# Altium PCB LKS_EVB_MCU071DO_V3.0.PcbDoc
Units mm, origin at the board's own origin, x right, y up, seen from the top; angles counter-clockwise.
Board outline 66.67 x 39.62 mm, 2 copper layers (Top Layer, Bottom Layer); 43 components, 55 nets, 188 pads, 243 vias.
Unrouted connection lines stored in the file: 4.
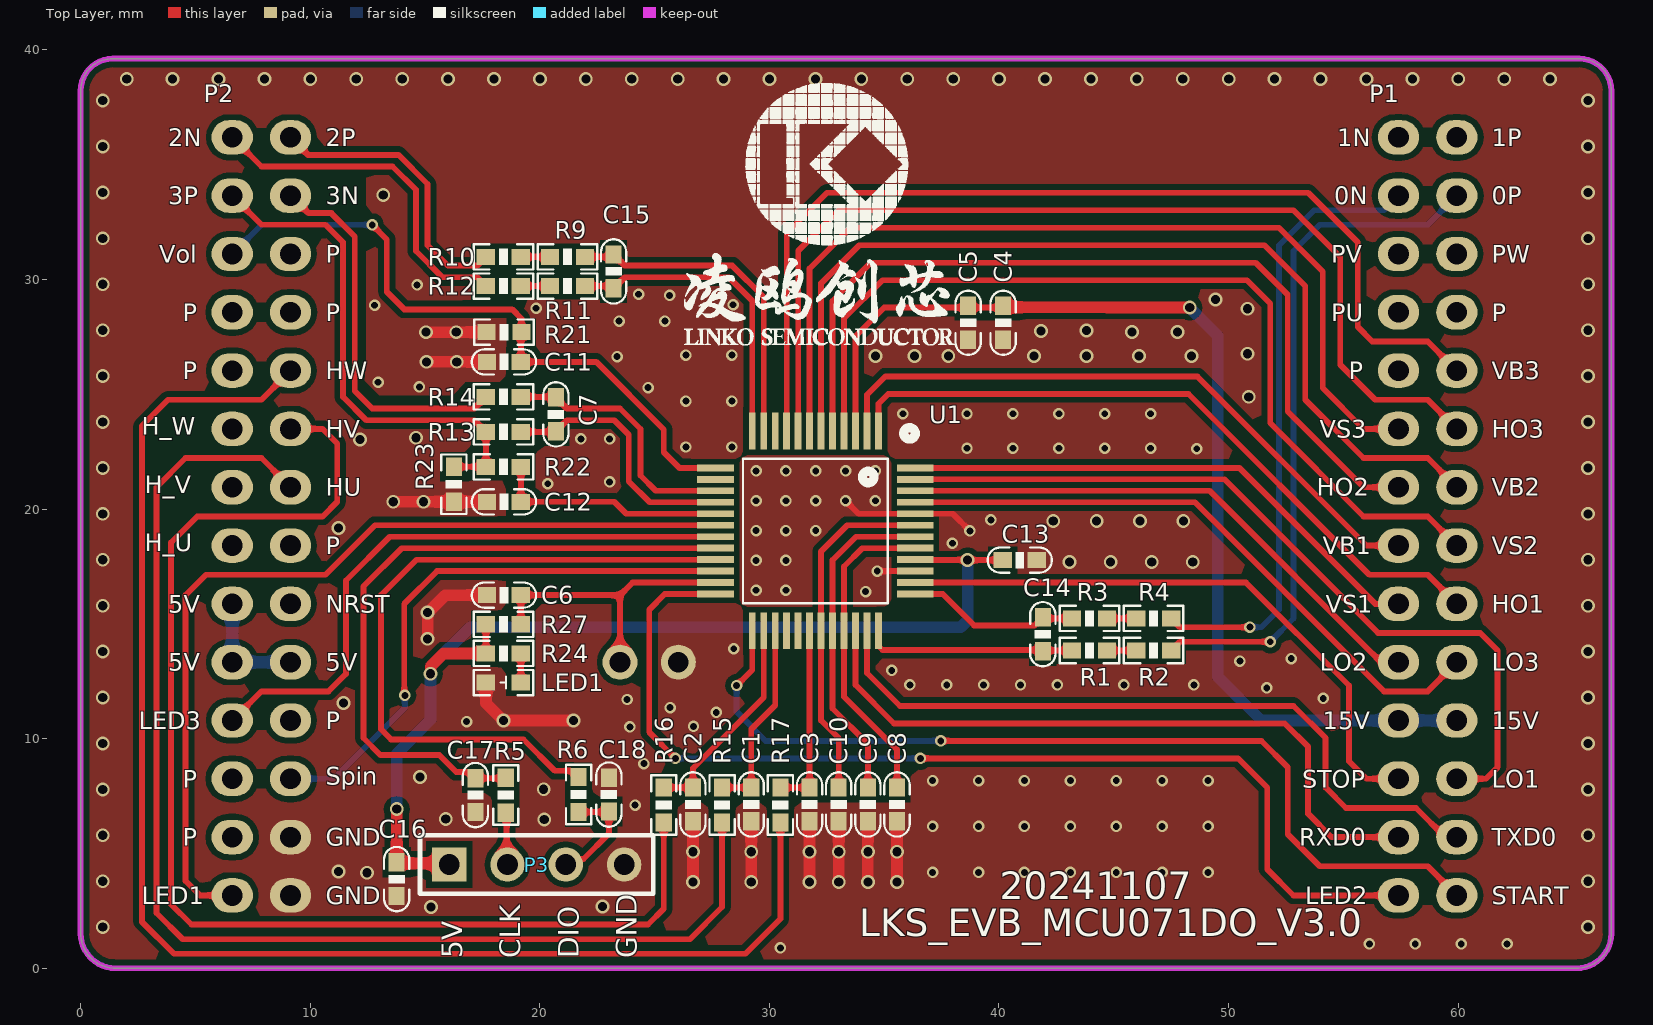
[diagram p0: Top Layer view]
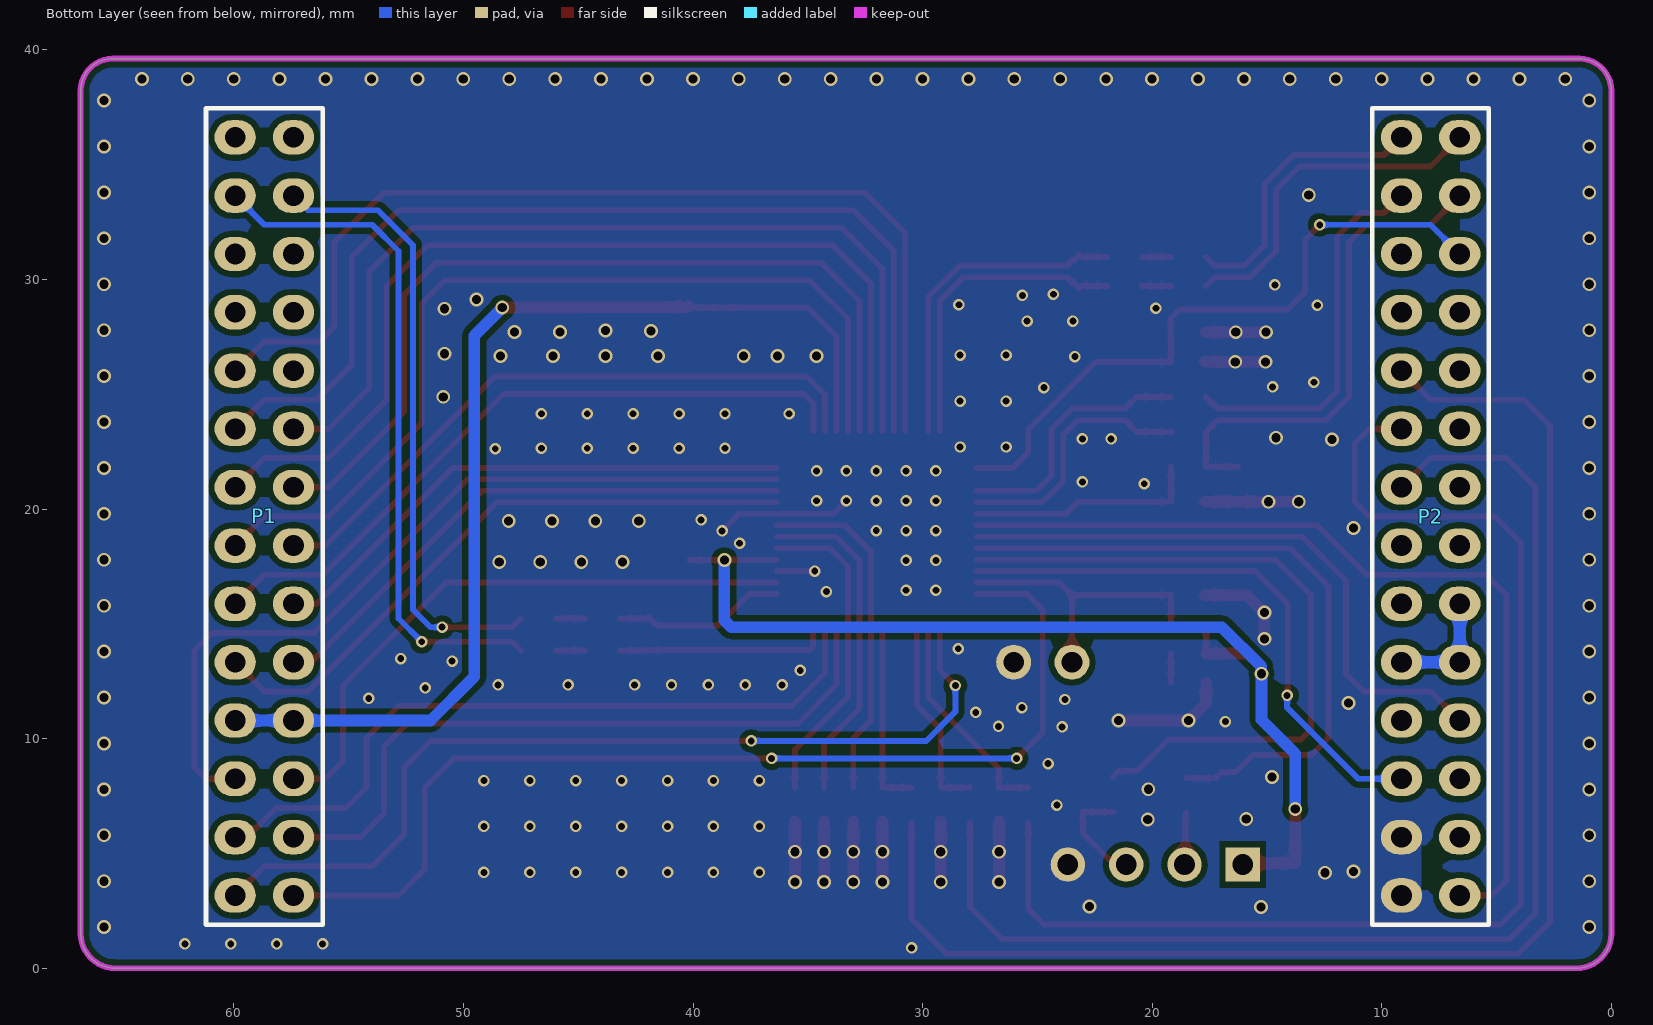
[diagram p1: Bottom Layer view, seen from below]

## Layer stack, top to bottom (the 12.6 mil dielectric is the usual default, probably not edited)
Top Solder: solder mask 0.0102, Solder Resist, Dk 3.5
Top Layer: signal copper 0.0356
Dielectric1: dielectric 0.32, FR-4, Dk 4.8
Bottom Layer: signal copper 0.0356
Bottom Solder: solder mask 0.0102, Solder Resist, Dk 3.5

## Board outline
0,1.524 0,38.227 cw(c1.397,38.227) 1.397,39.624 65.278,39.624 cw(c65.278,38.227) 66.675,38.227 66.675,1.524 cw(c65.151,1.524) 65.151,0 1.524,0 cw(c1.524,1.524)

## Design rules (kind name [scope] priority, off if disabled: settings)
Clearance Clearance_MCU [All] p1: gap=0.254 ignorepadtopadclearanceinfootprint=FALSE except(0.198: Arc-Arc Arc-Track Arc-SMDPad Track-Track Track-SMDPad SMDPad-SMDPad)
Clearance [All] p2: gap=0.254 ignorepadtopadclearanceinfootprint=FALSE
ComponentClearance [All] p1: gap=0 collisioncheckmode=3 verticalgap=0 showdistances=FALSE
FabricationTestpoint [(IsPad And (OnTopLayer Or OnBottomLayer))] p1: side=3 testpointundercomponent=TRUE minsize=1.016 maxsize=2.54 preferedsize=1.524 minholesize=0 maxholesize=1.016 preferedholesize=0.813 testpointgrid=0.025 allowsidetop=TRUE allowsidebottom=TRUE usegrid=TRUE gridtolerance=0
HoleSize [All] p1: absolutevalues=TRUE maxlimit=2.54 minlimit=0 maxpercent=80.000 minpercent=20.000
PolygonConnect PolygonConnect_1 [HasFootprint('HDR 2X14 顶层') vs InNet('GND')] p1: connectstyle=Direct reliefconductorwidth=0.508 reliefentries=4 polygonreliefangle="90 Angle" airgapwidth=0.254
PolygonConnect [All] p2: connectstyle=Direct reliefconductorwidth=0.254 reliefentries=4 polygonreliefangle="90 Angle" airgapwidth=0.254
RoomDefinition MCU [InComponentClass('Components Class1') vs False] p1: confinementstyle=ConfineIn formatcopy=TRUE lockcomponents=FALSE outline 25.857,28.296 27.381,29.82 27.381,32.893 30.432,32.893 32.003,34.464 35.995,34.464 35.995,29.664 41.427,24.232 49.479,24.232 51.841,21.869 49.378,19.406 42.977,19.406 34.315,10.744 26.34,10.744 26.34,12.065 22.885,15.519 23.266,15.9 23.266,28.169
RoutingVias [All] p1: holewidth=0.711 width=1.27 viastyle="Through Hole" minholewidth=0 minwidth=0.254 maxholewidth=0.711 maxwidth=1.27
SilkToSolderMaskClearance SilkscreenOverComponentPads [IsPad] p1: minsilkscreentomaskgap=0.254 clearancetoexposedcopper=TRUE
SolderMaskExpansion [All] p1: expansion=0.102 istentingtop=FALSE
Width [All] p1: maxlimit=2.54 minlimit=0.025 preferedwidth=0.254
26 further rules are at their usual default settings.

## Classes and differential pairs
component class "Components Class1": U1

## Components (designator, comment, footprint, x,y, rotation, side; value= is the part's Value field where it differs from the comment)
C1 "10nF/16V" 0603C 29.21,7.137 r270 top
C2 "10nF/16V" 0603C 26.67,7.137 r270 top
C3 "10nF/16V" 0603C 31.75,7.137 r270 top
C4 "10uF/25V" 0603C 40.183,28.118 r90 top
C5 "100nF/50V" 0603C 38.659,28.118 r90 top
C6 "100nF/50V" 0603C 18.44,16.256 r180 top
C7 "1uF/50V" 0603C 20.701,24.13 r90 top
C8 "1nF/50V" 0603C 35.56,7.137 r270 top
C9 "1nF/50V" 0603C 34.29,7.137 r270 top
C10 "1nF/50V" 0603C 33.02,7.137 r270 top
C11 "100nF/50V" 0603C 18.439,26.416 r0 top
C12 "1nF/50V" 0603C 18.439,20.32 r0 top
C13 "1uF/16V" 0603C 40.907,17.78 r180 top
C14 "100pF/50V" 0603C 41.91,14.554 r270 top
C15 "100pF/50V" 0603C 23.216,30.353 r90 top
C16 "100nF/50V" 0603C 13.767,3.886 r270 top
C17 "20pF/50V" 0603C 17.196,7.544 r90 top
C18 "20pF/50V" 0603C 23.009,7.569 r270 top
LED1 "LED" "LED 0603R" 18.415,12.446 r180 top
P1 "Header 14X2A" "HDR 2X14 顶层" 58.674,19.685 r180 bottom locked
P2 "Header 14X2A" "HDR 2X14 顶层" 7.874,19.685 r180 bottom locked
P3 "Header 4" "HDR 1X4" 16.053,4.521 r0 top
R1 "1K1%" 0603R 43.942,13.843 r180 top value=K
R2 "0R1%" 0603R 46.736,13.843 r180 top value=K
R3 "1K1%" 0603R 43.942,15.24 r180 top value=K
R4 "0R%" 0603R 46.736,15.24 r180 top value=K
R5 "120R1%" 0603R 18.517,7.544 r270 top value=K
R6 "120R1%" 0603R 21.688,7.569 r270 top value=K
R9 "1K1%" 0603R 21.209,30.988 r0 top value=K
R10 "0R1%" 0603R 18.415,30.988 r0 top value=K
R11 "1K1%" 0603R 21.209,29.718 r0 top value=K
R12 "0R1%" 0603R 18.415,29.718 r0 top value=K
R13 "1K1%" 0603R 18.415,23.368 r0 top value=K
R14 "1K1%" 0603R 18.415,24.892 r0 top value=K
R15 "2K" 0603R 27.94,7.112 r90 top value=K
R16 "2K" 0603R 25.4,7.112 r90 top value=K
R17 "2K" 0603R 30.48,7.112 r90 top value=K
R21 "1K1%" 0603R 18.439,27.71 r0 top value=K
R22 "1K1%" 0603R 18.415,21.844 r180 top value=K
R23 "10R" 0603R 16.256,21.082 r270 top value=K
R24 "330R" 0603R 18.415,13.716 r0 top value=K
R27 "10K1%" 0603R 18.415,14.986 r180 top value=K
U1 "LKS32MC071DOC8T8" TQFP48 32.004,19.05 r180 top locked

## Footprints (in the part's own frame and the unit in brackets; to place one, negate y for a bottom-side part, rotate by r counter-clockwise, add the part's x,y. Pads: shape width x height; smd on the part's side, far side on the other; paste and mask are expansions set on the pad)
0603C [mm] "电容"
  rect 0.8x0.7 smd: 1(-0.737,0) 2(0.738,0)
  silkscreen extent -1.4,-0.55 1.4,0.55, body extent -0.8,-0.41 0.8,0.41, height 0.81
0603R [mm] "电阻"
  rect 0.8x0.7 smd: 1(-0.762,0) 2(0.762,0)
  silkscreen extent -1.3,-0.55 1.3,0.55, body extent -0.8,-0.4 0.8,0.4, height 0.45
"HDR 1X4" [mm] "单排针 2.54mm"
  rect 1.5x1.5 hole 0.9: 1(0,0)
  round 1.5 hole 0.9: 2(2.54,0) 3(5.08,0) 4(7.62,0)
  silkscreen extent -1.27,-1.27 8.89,1.27, body extent -1.27,-1.27 8.89,1.27, height 8.5
"HDR 2X14 顶层" [mm] "双排针 2.54mm 顶层"
  oval 1.8x1.5 hole 0.9: 1(1.27,16.51) 2(1.27,13.97) 3(1.27,11.43) 4(1.27,8.89) 5(1.27,6.35) 6(1.27,3.81) 7(1.27,1.27) 8(1.27,-1.27) 9(1.27,-3.81) 10(1.27,-6.35) 11(1.27,-8.89) 12(1.27,-11.43) 13(1.27,-13.97) 14(1.27,-16.51) 15(-1.27,16.51) 16(-1.27,13.97) 17(-1.27,11.43) 18(-1.27,8.89) 19(-1.27,6.35) 20(-1.27,3.81) 21(-1.27,1.27) 22(-1.27,-1.27) 23(-1.27,-3.81) 24(-1.27,-6.35) 25(-1.27,-8.89) 26(-1.27,-11.43) 27(-1.27,-13.97) 28(-1.27,-16.51)
  silkscreen extent -2.54,-17.78 2.54,17.78, body extent -2.54,-17.78 2.54,17.78, height 8.5
"LED 0603R" [mm] "LED"
  rect 0.8x0.7 smd: 1(-0.762,0) 2(0.762,0)
  silkscreen extent -1.3,-0.55 1.3,0.55, body extent -0.8,-0.4 0.8,0.4, height 0.47
TQFP48 [mm] "MCU"
  rect 0.3x1.6 smd: 1(-2.75,-4.35) 2(-2.25,-4.35) 3(-1.75,-4.35) 4(-1.25,-4.35) 5(-0.75,-4.35) 6(-0.25,-4.35) 7(0.25,-4.35) 8(0.75,-4.35) 9(1.25,-4.35) 10(1.75,-4.35) 11(2.25,-4.35) 12(2.75,-4.35) 25(2.75,4.35) 26(2.25,4.35) 27(1.75,4.35) 28(1.25,4.35) 29(0.75,4.35) 30(0.25,4.35) 31(-0.25,4.35) 32(-0.75,4.35) 33(-1.25,4.35) 34(-1.75,4.35) 35(-2.25,4.35) 36(-2.75,4.35)
  rect 1.6x0.3 smd: 13(4.35,-2.75) 14(4.35,-2.25) 15(4.35,-1.75) 16(4.35,-1.25) 17(4.35,-0.75) 18(4.35,-0.25) 19(4.35,0.25) 20(4.35,0.75) 21(4.35,1.25) 22(4.35,1.75) 23(4.35,2.25) 24(4.35,2.75) 37(-4.35,2.75) 38(-4.35,2.25) 39(-4.35,1.75) 40(-4.35,1.25) 41(-4.35,0.75) 42(-4.35,0.25) 43(-4.35,-0.25) 44(-4.35,-0.75) 45(-4.35,-1.25) 46(-4.35,-1.75) 47(-4.35,-2.25) 48(-4.35,-2.75)
  silkscreen extent -4.35,-4.5 3.15,3.15, body extent -4.5,-4.5 4.5,4.5, height 1.05

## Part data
C1 C2 C3 C8 C9 C10: library part CAP, "Capacitor"
C4 C5 C6 C7 C11 C12 C13 C14 C15 C16 C17 C18: library part C, "Capacitor"
LED1: "LED_Light"
P1 P2: "Header, 14-Pin, Dual row"
P3: "Header, 4-Pin"
R1 R2 R3 R4 R5 R6 R9 R10 R11 R12 R13 R14 R15 R16 R17 R21 R22 R23 R24 R27: library part Res, "Resistor"
U1: "芯片"

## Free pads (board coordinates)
  round 1.524 hole 0.9: 0(26.035,13.335) 1(23.495,13.335)

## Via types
v1: diameter 0.6, hole 0.4, Top Layer to Bottom Layer, 132 vias
v2: diameter 0.5, hole 0.3, Top Layer to Bottom Layer, 111 vias

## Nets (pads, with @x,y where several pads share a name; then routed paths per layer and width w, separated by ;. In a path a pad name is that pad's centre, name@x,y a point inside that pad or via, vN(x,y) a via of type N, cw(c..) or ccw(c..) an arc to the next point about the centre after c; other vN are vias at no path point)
5V: C13.2 C16.1 P3.1 R24.1 R27.2 U1.40 | length 46.4
  Top Layer w0.254: R24.1 R27.2 ; U1.40 36.364,17.79 38.623,17.79 v1(38.633,17.78) C13.2
  Top Layer w0.508: C16.1@13.767,4.573 C16.1 ; v1(13.767,6.934) C16.1 ; v1(15.24,12.827) 15.258,12.845 15.258,13.149 15.824,13.716 R24.1 ; P3.1 16.002,4.572 13.818,4.572 13.792,4.598 C16.1
  Bottom Layer w0.508: v1(13.767,6.934) 13.767,9.347 15.24,10.82 v1(15.24,12.827) 15.258,12.845 15.258,13.149 16.967,14.859 38.336,14.859 38.633,15.157 v1(38.633,17.78)
+5V: P2.9 P2.10 P2.24 | length 5.1
  Bottom Layer w0.508: P2.9 P2.10 P2.24
+15V: C4.2 C5.2 P1.11 P1.25 U1.3 | length 53.6
  Top Layer w0.254: U1.3 33.754,27.531 35.003,28.78 43.18,28.78
  Top Layer w0.508: C4.2 40.241,28.797 48.292,28.797 v1(48.309,28.78) 44.704,28.78
  Bottom Layer w0.508: v1(48.309,28.78) 49.53,27.559 49.53,12.7 51.435,10.795 P1.11 P1.25
GND: C1.2 C2.2 C3.2 C4.1 C5.1 C6.2 C8.2 C9.2 C10.2 C11.1 C12.1 C13.1 C16.2 C17.1 C18.1 LED1.2 P2.16 P2.27 P2.28 P3.4 pad.0 R14.1 R21.1 R23.2 U1.39 U1.44 | length 58.4
  Top Layer w0.254: P2.16 9.159,33.655 9.921,32.893 10.922,32.893 11.938,31.877 11.938,25.146 12.7,24.384 17.145,24.384 R14.1 ; v2(33.32,20.366) 33.886,19.8 U1.44 37.985,19.8 v2(38.735,19.05) ; v2(34.699,17.3) U1.39
  Top Layer w0.508: v1(13.617,20.32) v1(14.937,20.32) R23.2 C12.1 ; v1(15.038,27.71) v1(16.358,27.71) R21.1 ; v1(15.064,26.416) v1(16.383,26.416) C11.1 ; v1(15.113,14.351) v1(15.113,15.494) 15.875,16.256 C6.2 ; LED1.2 17.653,11.557 v1(18.415,10.795) v1(21.463,10.795) ; v1(26.67,3.761) v1(26.67,5.08) C2.2 ; v1(29.21,3.761) v1(29.21,5.08) C1.2 ; v1(31.75,3.761) v1(31.75,5.08) C3.2 ; v1(33.02,3.761) v1(33.02,5.08) C10.2 ; v1(34.29,3.761) v1(34.29,5.08) C9.2 ; v1(35.56,3.761) v1(35.56,5.08) C8.2
  other v1: 0.965,1.795 65.659,1.795 15.265,2.667 22.733,2.692 0.965,3.795 65.659,3.795 12.471,4.166 11.227,4.216 0.965,5.795 65.659,5.795 20.193,6.477 15.9,6.502 0.965,7.795 65.659,7.795 20.168,7.798 14.783,8.331 0.965,9.795 65.659,9.795 11.455,11.557 0.965,11.795 65.659,11.795 0.965,13.795 65.659,13.795 0.965,15.795 65.659,15.795 43.078,17.704 44.865,17.704 46.651,17.704 48.438,17.704 0.965,17.795 65.659,17.795 11.227,19.177 42.367,19.482 44.255,19.482 46.143,19.482 48.031,19.482 0.965,19.795 65.659,19.795 0.965,21.795 65.659,21.795 12.167,23.038 14.605,23.114 0.965,23.795 65.659,23.795 50.876,24.892 0.965,25.795 65.659,25.795 34.62,26.67 36.322,26.67 37.795,26.67 41.529,26.67 43.815,26.67 46.101,26.67 48.387,26.67 50.825,26.772 45.796,27.711 47.777,27.711 41.834,27.762 0.965,27.795 43.815,27.788 65.659,27.795 50.825,28.727 49.428,29.134 0.965,29.795 65.659,29.795 0.965,31.795 65.659,31.795 13.183,33.68 0.965,33.795 65.659,33.795 0.965,35.795 65.659,35.795 0.965,37.795 65.659,37.795 2.007,38.735 4.007,38.735 6.007,38.735 8.007,38.735 10.007,38.735 12.007,38.735 14.007,38.735 16.007,38.735 18.007,38.735 20.007,38.735 22.007,38.735 24.007,38.735 26.007,38.735 28.007,38.735 30.007,38.735 32.007,38.735 34.007,38.735 36.007,38.735 38.007,38.735 40.007,38.735 42.007,38.735 44.007,38.735 46.007,38.735 48.007,38.735 50.007,38.735 52.007,38.735 54.007,38.735 56.007,38.735 58.007,38.735 60.007,38.735 62.007,38.735 64.007,38.735
  other v2: 30.48,0.889 56.134,1.067 58.134,1.067 60.134,1.067 62.134,1.067 37.109,4.179 39.109,4.179 41.109,4.179 43.109,4.179 45.109,4.179 47.109,4.179 49.109,4.179 37.109,6.179 39.109,6.179 41.109,6.179 43.109,6.179 45.109,6.179 47.109,6.179 49.109,6.179 24.155,7.112 37.109,8.179 39.109,8.179 41.109,8.179 43.109,8.179 45.109,8.179 47.109,8.179 49.109,8.179 24.536,8.915 23.927,10.516 26.695,10.541 16.815,10.744 27.686,11.151 25.679,11.354 23.8,11.709 54.127,11.76 51.664,12.217 36.119,12.344 37.725,12.344 39.332,12.344 40.938,12.344 42.545,12.344 45.441,12.344 48.489,12.344 35.331,12.979 50.495,13.386 52.73,13.487 28.448,13.919 34.188,16.408 29.42,16.466 30.72,16.466 29.42,17.766 30.72,17.766 37.973,18.517 29.42,19.066 30.72,19.066 32.02,19.066 39.649,19.533 29.42,20.366 30.72,20.366 32.02,20.366 34.62,20.366 20.345,21.107 23.038,21.184 29.42,21.666 30.72,21.666 32.02,21.666 33.32,21.666 34.62,21.666 48.616,22.631 38.608,22.655 40.608,22.655 42.608,22.655 44.608,22.655 46.608,22.655 26.365,22.708 28.365,22.708 21.793,23.063 23.038,23.063 35.814,24.155 38.608,24.155 40.608,24.155 42.608,24.155 44.608,24.155 46.608,24.155 26.365,24.708 28.365,24.708 24.714,25.298 14.757,25.324 12.954,25.527 23.368,26.645 26.365,26.708 28.365,26.708 23.451,28.194 25.451,28.194 19.837,28.753 12.802,28.88 28.423,28.905 25.654,29.312 24.308,29.362 14.656,29.769
HALL_U: C1.1 R15.2 U1.27 | length 8.5
  Top Layer w0.254: R15.2 C1.1 29.21,10.414 30.254,11.458 U1.27
HALL_V: C2.1 R16.2 U1.26 | length 9.4
  Top Layer w0.254: R16.2 C2.1 26.67,8.712 29.754,11.796 U1.26
HALL_W: C3.1 R17.2 U1.30 | length 8.1
  Top Layer w0.254: R17.2 C3.1 31.752,7.876 31.752,14.698 U1.30
HO1: P1.23 U1.1 | length 30.3
  Top Layer w0.254: U1.1 34.754,24.594 35.179,25.019 48.26,25.019 56.134,17.145 58.674,17.145 P1.23
HO2: P1.7 U1.5 | length 38
  Top Layer w0.254: U1.5 32.754,29.071 34.417,30.734 51.181,30.734 52.578,29.337 52.578,24.257 55.88,20.955 P1.7
HO3: P1.20 U1.8 | length 44
  Top Layer w0.254: U1.8 31.254,31.254 33.02,33.02 52.832,33.02 54.864,30.988 54.864,26.289 56.388,24.765 58.674,24.765 P1.20
HU: P2.21 R15.1 | length 54.9
  Top Layer w0.254: P2.21@9.207,21.018 P2.21 7.874,22.225 4.572,22.225 3.302,20.955 3.302,2.413 4.445,1.27 26.543,1.27 27.94,2.667 R15.1
HV: P2.20 R16.1 | length 54.4
  Top Layer w0.254: P2.20 10.541,23.495 11.176,22.86 11.176,20.32 10.541,19.685 5.08,19.685 3.937,18.542 3.937,2.794 4.826,1.905 24.714,1.905 25.4,2.591 R16.1
HW: P2.19 R17.1 | length 62.3
  Top Layer w0.254: P2.19 7.874,24.765 3.81,24.765 2.667,23.622 2.667,2.032 4.064,0.635 28.956,0.635 30.48,2.159 R17.1
LED1: P2.14 U1.18 | length 39.1
  Top Layer w0.254: P2.14 5.207,3.175 4.572,3.81 4.572,16.256 5.461,17.145 10.668,17.145 12.823,19.3 U1.18
LED2: P1.14 U1.24 | length 46.2
  Top Layer w0.254: v2(25.908,9.144) 24.765,10.287 24.765,15.621 25.444,16.3 U1.24 ; v2(36.576,9.144) 50.419,9.144 51.689,7.874 51.689,4.318 52.832,3.175 P1.14
  Bottom Layer w0.254: v2(25.908,9.144) v2(36.576,9.144)
LED3: P2.11 U1.19 | length 26.7
  Top Layer w0.254: P2.11 7.874,12.065 10.795,12.065 11.557,12.827 11.557,16.891 13.466,18.8 U1.19
LO1: P1.26 U1.47 | length 35.5
  Top Layer w0.254: U1.47 49.82,21.3 56.515,14.605 60.96,14.605 61.722,13.843 61.722,8.763 61.214,8.255 P1.26
LO2: P1.10 U1.46 | length 24.1
  Top Layer w0.254: U1.46 49.177,20.8 56.642,13.335 P1.10
LO3: P1.24 U1.45 | length 27.5
  Top Layer w0.254: U1.45 48.534,20.3 56.769,12.065 58.674,12.065 P1.24
NetC18_2: C18.2 P3.3 R6.2 | length 4.7
  Top Layer w0.254: P3.3 21.371,4.76 21.905,4.76 23.009,5.864 C18.2 22.985,6.807 R6.2
NetLED1_1: LED1.1 R24.2 | length 1.3
  Top Layer w0.254: LED1.1 R24.2
NetP3_2: P3.2 R5.2 | length 2.3
  Top Layer w0.254: R5.2 18.555,6.744 18.555,4.559 P3.2
NetR1_1: R1.1 R2.2 | length 1.3
  Top Layer w0.254: R1.1 R2.2
NetR3_1: R3.1 R4.2 | length 1.3
  Top Layer w0.254: R3.1 R4.2
NetR9_1: R9.1 R10.2 | length 1.3
  Top Layer w0.254: R10.2 R9.1
NetR11_1: R11.1 R12.2 | length 1.3
  Top Layer w0.254: R12.2 R11.1
NRST: C6.1 pad.1 R27.1 U1.23 | length 12.9
  Top Layer w0.254: R27.1 C6.1 23.495,16.256 ; pad.1 23.495,16.256 ; U1.23 24.039,16.8 23.495,16.256
OC: C12.2 R22.1 U1.17 | length 10.2
  Top Layer w0.254: R22.1 C12.2 23.241,20.32 23.761,19.8 U1.17
OPA0_IN: C14.1 R3.2 U1.37 | length 7.6
  Top Layer w0.254: U1.37 37.548,16.3 38.92,14.928 41.547,14.928 41.637,15.018 41.687,15.018 41.91,15.241 C14.1 41.961,15.24 R3.2
OPA0_IP: C14.2 R1.2 U1.36 | length 9.2
  Top Layer w0.254: U1.36 34.777,14.677 34.777,14.015 34.926,13.866 41.86,13.866 C14.2 41.937,13.843 R1.2
OPA2_IN: C15.1 R11.2 U1.12 | length 13.7
  Top Layer w0.254: R11.2 23.114,29.718 C15.1 23.216,29.666 23.439,29.889 23.489,29.889 23.698,30.099 28.236,30.099 29.254,29.081 U1.12
OPA2_IP: C15.2 R9.2 U1.11 | length 14.5
  Top Layer w0.254: R9.2 23.113,30.988 C15.2 23.216,31.041 23.439,30.818 23.489,30.818 23.7,30.607 28.384,30.607 29.754,29.237 U1.11
OPA3_IN: C7.2 R14.2 U1.15 | length 11.4
  Top Layer w0.254: R14.2 20.677,24.892 C7.2 21.185,24.384 23.495,24.384 24.384,23.495 24.384,21.463 25.047,20.8 U1.15
OPA3_IP: C7.1 R13.2 U1.16 | length 11.4
  Top Layer w0.254: R13.2 20.676,23.368 C7.1 21.184,23.876 23.241,23.876 23.876,23.241 23.876,21.209 24.785,20.3 U1.16
PGND: P1.1 P1.2 P2.1 P2.2 R4.1 R12.1 R13.1 R22.2 R23.1 | length 64.6
  Top Layer w0.254: P2.2 7.874,32.385 10.668,32.385 11.43,31.623 11.43,24.892 12.446,23.876 17.145,23.876 R13.1 R22.2 R23.1 ; P2.1 7.874,34.925 13.589,34.925 14.605,33.909 14.605,31.242 15.748,30.099 17.272,30.099 R12.1 ; R4.1 47.879,14.859 v2(50.927,14.859)
  Bottom Layer w0.254: v2(50.927,14.859) 51.435,14.859 52.197,15.621 52.197,31.496 53.721,33.02 56.769,33.02 P1.2
PU: C8.1 U1.33 U1.41 | length 14
  Top Layer w0.254: C8.1 35.56,9.525 33.254,11.831 33.254,17.506 34.048,18.3 U1.41
PV: C9.1 U1.32 U1.42 | length 14.6
  Top Layer w0.254: C9.1 34.29,9.779 32.754,11.315 32.754,17.78 33.774,18.8 U1.42
PW: C10.1 U1.31 U1.43 | length 15.2
  Top Layer w0.254: C10.1 33.02,10.033 32.254,10.799 U1.31 32.254,18.161 33.393,19.3 U1.43
RXD0: P1.13 U1.34 | length 30.5
  Top Layer w0.254: U1.34 33.754,12.347 35.433,10.668 52.451,10.668 53.467,9.652 53.467,6.731 54.483,5.715 P1.13
SPIN: P2.26 U1.22 | length 25.1
  Top Layer w0.254: P2.26 P2.26@9.294,8.255 ; v2(14.122,11.887) 14.097,11.913 14.097,15.875 15.522,17.3 U1.22
  Bottom Layer w0.254: P2.26 11.024,8.255 14.122,11.354 v2(14.122,11.887)
START1: P1.28 U1.25 | length 40.2
  Top Layer w0.254: v2(28.575,12.319) 29.254,12.998 U1.25 ; v2(37.465,9.906) 51.435,9.906 52.578,8.763 52.578,5.842 53.975,4.445 58.674,4.445 P1.28
  Bottom Layer w0.254: v2(28.575,12.319) 28.575,11.176 29.845,9.906 v2(37.465,9.906)
STOP1: P1.12 U1.38 | length 26.5
  Top Layer w0.254: U1.38 50.764,16.8 55.245,12.319 55.245,9.017 56.007,8.255 P1.12
SWCLK: C17.2 R5.1 U1.20 | length 29.6
  Top Layer w0.254: R5.1 18.493,8.282 C17.2 17.196,8.332 16.973,8.555 16.363,8.555 15.621,9.296 13.056,9.296 12.319,10.033 12.319,16.637 13.982,18.3 U1.20
SWDIO: R6.1 U1.21 | length 30.6
  Top Layer w0.254: R6.1 21.688,8.381 21.465,8.604 20.657,8.604 19.291,9.97 13.525,9.97 13.081,10.414 13.081,16.256 14.625,17.8 U1.21
TXD0: P1.27 U1.35 | length 31.8
  Top Layer w0.254: U1.35 34.254,12.863 35.687,11.43 52.832,11.43 54.229,10.033 54.229,7.874 55.118,6.985 58.166,6.985 59.436,5.715 P1.27
UP-: P2.15 R10.1 | length 12.5
  Top Layer w0.254: P2.15 9.906,35.433 13.843,35.433 15.113,34.163 15.113,31.496 16.002,30.607 17.272,30.607 R10.1
VB1: P1.8 U1.2 | length 28.1
  Top Layer w0.254: U1.2 34.254,24.983 35.052,25.781 48.641,25.781 56.007,18.415 P1.8
VB2: P1.21 U1.6 | length 42.1
  Top Layer w0.254: U1.6 32.254,29.841 33.909,31.496 51.562,31.496 53.34,29.718 53.34,24.765 55.88,22.225 58.674,22.225 P1.21
VB3: P1.19 U1.9 | length 43.9
  Top Layer w0.254: U1.9 30.754,32.024 32.512,33.782 53.467,33.782 55.626,31.623 55.626,27.94 56.261,27.305 58.674,27.305 P1.19
VOL_ADC: C11.2 P2.3 R21.2 U1.13 | length 29.2
  Top Layer w0.254: P2.3 P2.3@6.754,31.115 ; v2(12.7,32.385) 13.335,31.75 13.335,29.464 14.097,28.702 18.796,28.702 19.201,28.297 R21.2 19.177,27.686 C11.2 22.454,26.416 25.4,23.47 25.4,22.479 26.079,21.8 U1.13
  Bottom Layer w0.254: P2.3 7.874,32.385 v2(12.7,32.385)
VP-: P1.15
VS1: P1.9 U1.48 | length 23.5
  Top Layer w0.254: U1.48 50.463,21.8 56.388,15.875 P1.9
VS2: P1.22 U1.4 | length 40.1
  Top Layer w0.254: U1.4 33.254,28.301 34.925,29.972 50.8,29.972 51.816,28.956 51.816,23.749 55.88,19.685 58.674,19.685 P1.22
VS3: P1.6 U1.7 | length 40.1
  Top Layer w0.254: U1.7 31.754,30.484 33.528,32.258 52.197,32.258 54.102,30.353 54.102,25.273 55.88,23.495 P1.6
WP-: P1.16 R2.1 | length 30
  Top Layer w0.254: R2.1 47.879,14.224 v2(51.816,14.224)
  Bottom Layer w0.254: v2(51.816,14.224) 52.832,15.24 52.832,31.242 53.975,32.385 58.674,32.385 P1.16
pads on no net: P1.3 P1.4 P1.5 P1.17 P1.18 P2.4 P2.5 P2.6 P2.7 P2.8 P2.12 P2.13 P2.17 P2.18 P2.22 P2.23 P2.25 U1.10 U1.14 U1.28 U1.29

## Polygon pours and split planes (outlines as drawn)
GND on Bottom Layer "Bottom Layer-No Net 1" (solid, remove dead copper, pour order 13): 0,39.624 0,0 66.675,0 66.675,39.624
GND on Top Layer "Bottom Layer-No Net 1" (solid, remove dead copper, pour order 12): 0,39.624 0,0 66.675,0 66.675,39.624

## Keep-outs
Keep-Out Layer:
  the board outline again, w0.254

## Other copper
Top Layer:
  pour cut-out: 13.005,24.968 12.372,25.601 12.446,26.416 12.446,34.442 11.354,34.442 10.389,35.408 7.417,35.408 7.417,32.842 8.255,32.004 11.049,32.004 11.049,25.679 12.756,23.972 18.523,23.972 18.523,25.496 18.467,25.552 16.739,25.552 16.739,25.502 16.205,24.968
Bottom Layer:
  pour cut-out: 8.255,5.334 8.255,3.429 7.493,3.429 7.493,5.207 7.366,5.334
  pour cut-out: 6.604,36.195 6.604,31.115 10.414,31.115 10.414,36.195

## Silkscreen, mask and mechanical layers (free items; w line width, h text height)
Top Overlay:
  drawing of 144 lines, arcs and shapes, not listed
  text "2N" at 3.81,35.814 h0.76
  text "2P" at 10.668,35.814 h0.76
  text "1N" at 54.737,35.814 h0.76
  text "1P" at 61.468,35.814 h0.76
  text "3P" at 3.81,33.274 h0.76
  text "3N" at 10.668,33.274 h0.76
  text "0N" at 54.61,33.274 h0.76
  text "0P" at 61.468,33.274 h0.76
  text "Vol" at 3.429,30.734 h0.76
  text "P" at 10.668,30.734 h0.76
  text "PV" at 54.483,30.734 h0.76
  text "PW" at 61.468,30.734 h0.76
  text "P" at 4.445,28.194 h0.76
  text "P" at 10.668,28.194 h0.76
  text "PU" at 54.483,28.194 h0.76
  text "P" at 61.468,28.194 h0.76
  text "P" at 4.445,25.654 h0.76
  text "HW" at 10.668,25.654 h0.76
  text "P" at 55.245,25.654 h0.76
  text "VB3" at 61.468,25.654 h0.76
  text "H_W" at 2.667,23.241 h0.76
  text "HV" at 10.668,23.114 h0.76
  text "VS3" at 53.975,23.114 h0.76
  text "HO3" at 61.468,23.114 h0.76
  text "H_V" at 2.794,20.701 h0.76
  text "HU" at 10.668,20.574 h0.76
  text "HO2" at 53.848,20.574 h0.76
  text "VB2" at 61.468,20.574 h0.76
  text "H_U" at 2.794,18.161 h0.76
  text "P" at 10.668,18.034 h0.76
  text "VB1" at 54.102,18.034 h0.76
  text "VS2" at 61.468,18.034 h0.76
  text "5V" at 3.81,15.494 h0.76
  text "NRST" at 10.668,15.494 h0.76
  text "VS1" at 54.229,15.494 h0.76
  text "HO1" at 61.468,15.494 h0.76
  text "5V" at 3.81,12.954 h0.76
  text "5V" at 10.668,12.954 h0.76
  text "LO2" at 53.975,12.954 h0.76
  text "LO3" at 61.468,12.954 h0.76
  text "LED3" at 2.54,10.414 h0.76
  text "P" at 10.668,10.414 h0.76
  text "15V" at 54.102,10.414 h0.76
  text "15V" at 61.468,10.414 h0.76
  text "Spin" at 10.668,8.001 h0.76
  text "P" at 4.445,7.874 h0.76
  text "STOP" at 53.213,7.874 h0.76
  text "LO1" at 61.468,7.874 h0.76
  text "P" at 4.445,5.334 h0.76
  text "GND" at 10.668,5.334 h0.76
  text "RXD0" at 53.086,5.334 h0.76
  text "TXD0" at 61.468,5.334 h0.76
  text "LED1" at 2.667,2.794 h0.76
  text "GND" at 10.668,2.794 h0.76
  text "LED2" at 53.34,2.794 h0.76
  text "START" at 61.468,2.794 h0.76
  text "20241107" at 40.03,2.616 h2.03
  text "LKS_EVB_MCU071DO_V3.0" at 33.909,1.016 h2.03
  text "5V" at 16.612,0.432 h0.89 r90
  text "CLK" at 19.152,0.432 h0.89 r90
  text "DIO" at 21.692,0.432 h0.89 r90
  text "GND" at 24.232,0.432 h0.89 r90
Mechanical 1:
  the board outline again, w0.254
